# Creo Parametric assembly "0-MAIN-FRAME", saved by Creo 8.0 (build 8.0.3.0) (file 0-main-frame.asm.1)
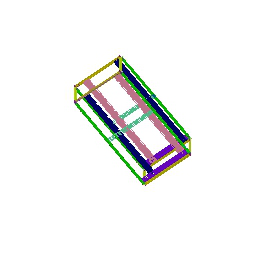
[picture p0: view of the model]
Units: millimeter Newton Second (mmNs); MM, TONNE, SECS

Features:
  1. datum plane "ADTM1"
  2. datum plane "ADTM2"
  3. datum plane "ADTM3"
  4. coordinate system
  5. component "1_POST-MAIN"
  6. component "1_POST-MAIN"
  7. component
  8. component
  9. component
  10. component "1_POST-MAIN"
  11. component "1_POST-MAIN"
  12. component "1_POST-FRONT"
  13. component "1_POST-FRONT"
  14. component "1_POST-FRONT"
  15. component "1_POST-FRONT"
  16. component "1_POST-SIDE"
  17. component "1_POST-SIDE"
  18. component "1_POST-SIDE"
  19. component "1_POST-SIDE"
  20. component "1_FLANGE-R"
  21. component "1_FLANGE-L"
  22. component "1_FLANGE-R"
  23. component "1_FLANGE-L"
  24. component "1_FRAME-SIDE"
  25. component "1_FRAME-SIDE"
  26. component "1_FRAME-BOTTOM"
  27. component "1_FRAME-BOTTOM"
  28. component "1_FRONT_DOOR_LATCH"
  29. component "1_CORNER-FIX"
  30. component "1_CORNER-FIX"
  31. component "1_CORNER-FIX"
  32. component "1_CORNER-FIX"
  33. component "1_CORNER-FIX"
  34. component "1_CORNER-FIX"
  35. component "1_CORNER-FIX"
  36. component "1_CORNER-FIX"
  37. component "3_NUT-M5"
  38. component
  39. component
  40. component
  41. component
  42. component "1_CORNER-FIX3"
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
Other components: 1_CORNER-FIX3, 1_CORNER-FIX2, 1_CORNER-FIX3, 1_CORNER-FIX3, 1_CORNER-FIX3, PRT0001, PRT0001, FIX5, FIX5, FIX5, FIX5, FIX5, FIX5, FIX5, FIX5, FIX5, FIX5, FIX5, FIX5, FIX5, FIX5, FIX5, FIX5

Other named items: ACS0, REP0001, REP0002, VIS0001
